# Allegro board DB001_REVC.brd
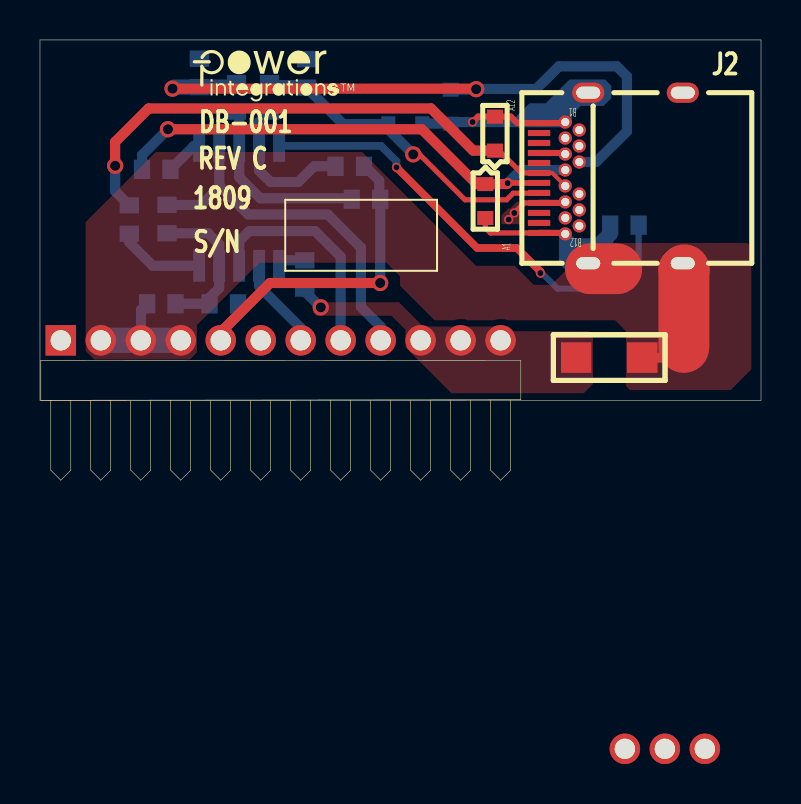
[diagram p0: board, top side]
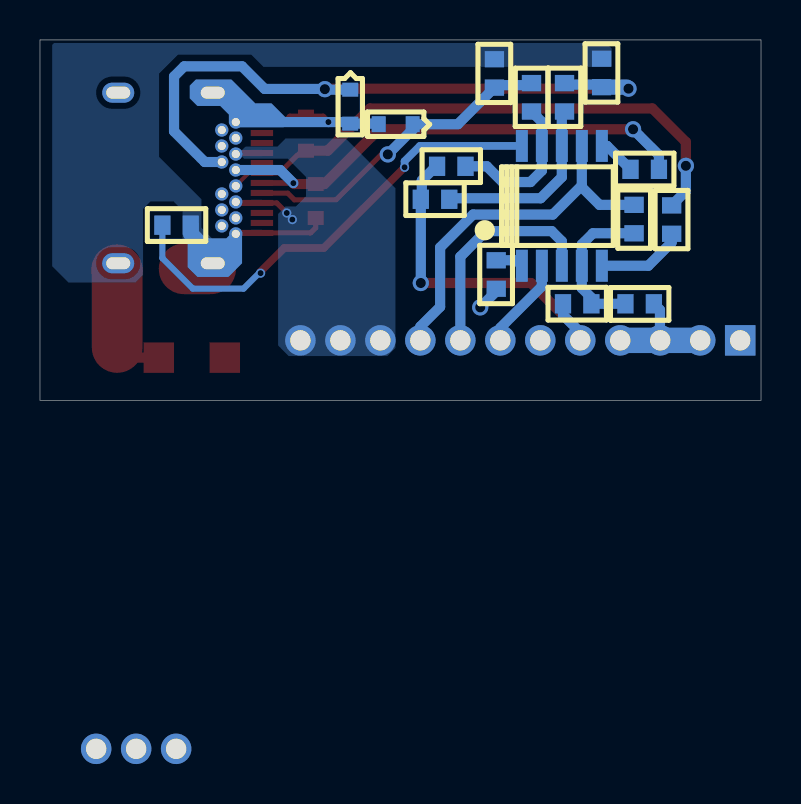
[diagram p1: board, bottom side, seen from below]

Outline 36.07 x 18.03 mm; copper layers: TOP, BOTTOM. Coordinates in mm from the lower left corner of the outline.
Outline path: 0,18.03 0,0 36.07,0 36.07,18.03 0,18.03

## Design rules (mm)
constraint set DEFAULT: min track width 0.508

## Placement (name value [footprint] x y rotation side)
C1  270 pF  [PISMC0603]  13.33 17.07 270 bottom
C2  270 pF  [PISMC0603]  7.98 17.09 270 bottom
C3  2.2 uF  [PISMC1206]  26.82 2.13 0 top
C18  2.2 uF  [PISMC0603]  6.35 8.36 90 bottom
C19  270 pF  [PISMC0603]  14.78 11.71 0 bottom
C20  270 pF  [PISMC0603]  15.6 10.06 0 bottom
D1  DZ2J240M0L  [PI_SM_D_SSMINI2P]  20.55 15.54 270 bottom
D2  DZ2J240M0L  [PI_SM_D_SSMINI2P]  17.42 13.82 0 bottom
D3  DZ2J240M0L  [PI_SM_D_SSMINI2P]  22.28 10.82 270 top
D4  DZ2J240M0L  [PI_SM_D_SSMINI2P]  22.76 12.5 90 top
J1  CON15  [PI_UNSHROUD_2MM_15PRA]  1.04 3 0 bottom
J2  CON24_USB_C  [PI_CONN_USBC_WURTH]  26.97 11.13 90 top
NOREF  -  []  7.09 17.42 0 top
NOREF#2  -  []  0 0 90 top
NOREF#3  -  []  -250.16 -145.39 0 top
NOREF#4  -  []  -172.35 53.62 0 top
NOREF#5  -  []  0 18.03 0 top
R1  22  [PISMR0603]  11.48 14.45 90 bottom
R2  22  [PISMR0603]  9.83 15.88 270 bottom
R3  22  [PISMR0603]  4.47 9.75 270 bottom
R4  22  [PISMR0603]  6.53 11.56 180 bottom
R13  1 k  [PISMR0603]  13.25 7.01 270 bottom
R14  0.0  [PISMR0603]  8.48 4.83 0 bottom
R15  0.0  [PISMR0603]  6.78 4.83 180 bottom
RT1  100 k  [PISMR0603]  28.52 8.76 0 bottom
U1  WT6635P  [PISMSOP10]  11.96 6.73 180 bottom

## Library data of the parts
C1-C3 C18-C20 = CAP NP
D1-D4 = DIODE_ZENER
J1 = CON15
J2 = CON24_USB
R1-R4 R13-R15 = R
RT1 = THERMISTOR
U1 = WT6635P-10

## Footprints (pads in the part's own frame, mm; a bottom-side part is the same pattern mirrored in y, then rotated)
PI_CONN_USBC_WURTH
  oval 1.001x1.6 hole 0.599x1.199: (-4.27,-0.45) (-4.27,-5.179) (4.27,-0.45) (4.27,-5.179)
  round 0.66 hole 0.406: (-1.999,0.701) (1.999,0.701) B1(2.799,0.701) B2(2.4,0) B3(1.6,0) B4(1.199,0.701) B5(0.8,0) B6(0.399,0.701) B7(-0.399,0.701) B8(-0.8,0) B9(-1.199,0.701) B10(-1.6,0) B11(-2.4,0) B12(-2.799,0.701)
  rect 0.305x1.118 smd: A1(-2.751,2.009) A2(-2.25,2.009) A3(-1.75,2.009) A4(-1.25,2.009) A5(-0.749,2.009) A6(-0.249,2.009) A7(0.249,2.009) A8(0.749,2.009) A9(1.25,2.009) A10(1.75,2.009) A11(2.25,2.009) A12(2.751,2.009)
PI_SM_D_SSMINI2P
  rect 0.699x0.8 smd: 1(0,0) 2(1.699,0)
PI_UNSHROUD_2MM_15PRA
  rect 1.524x1.524 hole 1.016: 1(0,0)
  round 1.524 hole 1.016: 2(2,0) 3(4,0) 4(6,0) 5(8,0) 6(10,0) 7(12,0) 8(14,0) 9(16,0) 10(18,0) 11(20,0) 12(22,0) 13(28.216,20.447) 14(30.216,20.447) 15(32.216,20.447)
PISMC0603
  rect 0.813x0.965 smd: 1(0,0) 2(1.422,0)
PISMC1206
  rect 1.524x1.524 smd: 1(0,0) 2(3.302,0)
PISMR0603
  rect 0.813x0.965 smd: 1(0,0) 2(1.422,0)
PISMSOP10
  rect 0.599x1.6 smd: 1(0,0) 2(1.001,0) 3(1.999,0) 4(3,0) 5(4,0) 6(4,5.999) 7(3,5.999) 8(1.999,5.999) 9(1.001,5.999) 10(0,5.999)

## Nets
GND: C1.1 C2.1 C3.2 D1.2 D2.2 D3.2 D4.2 J1.2 J1.3 J1.4 J2.A1 J2.A12 J2.B1 J2.B12 R15.2 RT1.1
GND_SIGNAL: C19.2 C20.2 J1.5 R14.2
VBUS_IN: J1.1
VBUS_OUT: C3.1 J1.10 J1.11 J1.12 J2.A4 J2.A9 J2.B4 J2.B9(VBUS4) R13.2
BPS: J1.6
SCL: J1.7 U1.2
SDA: J1.8 U1.3
UVCC: C18.2 J1.9 U1.7
N12116712: C2.2 D1.1 J2.B5 R2.1
N12116716: C1.2 D2.1 J2.A5 R1.2
N12116772: RT1.2 U1.10
N12116776: D3.1 J2.A6 J2.B6 R4.2
N12116788: R13.1 U1.1
N12116812: D4.1 J2.A7 J2.B7 R3.1
N12116850: C19.1 R1.1 U1.9
N12116916: C20.1 R2.2 U1.8
N12116972: C18.1 R14.1 R15.1 U1.4(VSS)
N12121431: R3.2 U1.5
N12121586: R4.1 U1.6

Pads without a net: J1 13 14 15; J2 A2 A3 A8 A10 A11 B2 B3 B8 B10 B11

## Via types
v1: diameter 0.813, hole 0.508, TOP to BOTTOM, 7 vias
v2: diameter 0.457, hole 0.305, TOP to BOTTOM, 6 vias

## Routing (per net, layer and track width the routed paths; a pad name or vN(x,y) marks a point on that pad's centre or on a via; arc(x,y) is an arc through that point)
GND: length 32.7
  TOP w0.254: J2.A1 22.53,8.37 22.28,8.63 D3.2
  TOP w0.305: J2.A1 26.23,8.37 J2.B12 ; J2.B1 26.23,13.88 J2.A12 23.88,13.88 23.56,14.2 D4.2 21.91,14.2 v2(21.64,13.92)
  TOP w0.508: C3.2 31.7,2.13 32.21,2.64
  TOP w2.54: 27.53,6.58 28.85,6.58 ; 32.21,2.64 32.21,6.5 32.23,6.53
  BOTTOM w0.508: R15.2 5.05,4.52 5.05,3.01 J1.3 ; D2.2 19.15,13.85 D1.2 20.63,13.92 v2(21.64,13.92) J2.B1
  BOTTOM w0.762: RT1.1 28.52,8.33 27.03,6.83
  BOTTOM w1.27: 7.04,3 J1.3 J1.2 3.04,3
GND_SIGNAL: length 17.8
  TOP w0.508: v1(17.02,5.87) 11.51,5.87 9.04,3.4 J1.5
  BOTTOM w0.508: C19.2 16.26,11.71 16.97,11 16.97,10.11 C20.2 v1(17.02,5.87) ; J1.5 9.04,3.4 9.91,4.27 R14.2
VBUS_OUT: length 5.4
  TOP w0.254: v2(23.72,9.37) 24.23,9.88 J2.A4
  TOP w0.305: J2.A9 26.22,12.37 J2.B4 ; J2.A4 26.22,9.88 J2.B9
  BOTTOM w0.508: v1(14.05,4.65) 13.25,5.45 R13.2
  vias: v2(23.44,9.04)
SCL: length 4.6
  BOTTOM w0.254: 13.04,3 J1.7
  BOTTOM w0.508: U1.2 10.96,5.7 13.04,3.62 13.04,3
SDA: length 11.2
  BOTTOM w0.508: J1.8 15.04,7.18 13.76,8.47 10.47,8.47 9.96,7.96 U1.3
UVCC: length 18.5
  BOTTOM w0.508: 8.96,10.75 10.41,9.3 14.4,9.3 16.05,7.65 16.05,4.67 17.04,3.69 J1.9 ; 8.96,10.75 8.96,10.67 8.08,9.78 C18.2 ; 8.96,10.75 U1.7
N12116712: length 33.9
  TOP w0.508: v1(21.82,15.57) 21.79,15.6 v1(6.63,15.6)
  BOTTOM w0.508: D1.1 21.75,15.54 21.82,15.62 ; 21.82,15.62 21.82,15.58 v1(21.82,15.57) ; 21.82,15.62 21.86,15.58 24.83,15.58 25.96,16.71 28.85,16.71 29.36,16.21 29.36,13.46 27.83,11.93 J2.B5 ; C2.2 8.1,15.8 9.75,15.8 R2.1 ; v1(6.63,15.6) 6.71,15.67
  BOTTOM w0.762: 6.71,15.67 C2.2
N12116716: length 16.2
  TOP w0.254: v1(18.67,12.31) 18.99,12.31 21.26,10.03 23.34,10.03 23.67,10.36 24.95,10.36 J2.A5
  BOTTOM w0.508: v1(18.67,12.31) 17.42,13.55 D2.1 15.16,13.82 C1.2 13.21,15.77 11.58,15.77 R1.2
N12116772: length 23.4
  TOP w0.381: v2(17.83,11.66) 21.87,7.62 23.85,7.62 25.03,6.44 v2(25.03,6.36)
  BOTTOM w0.305: v2(25.03,6.36) 25.11,6.36 25.88,5.59 28.42,5.59 29.95,7.11 RT1.2
  BOTTOM w0.381: v2(17.83,11.66) 17.83,11.96 17.06,12.73 U1.10
N12116776: length 27.1
  TOP w0.254: 23.31,10.87 23.32,10.87 24.96,10.87 J2.A6 23.4,10.88 v2(23.39,10.87)
  TOP w0.508: 23.39,10.87 v2(23.39,10.87) 23.35,10.82 D3.1 21.84,10.82 19.1,13.56 v1(6.4,13.56)
  BOTTOM w0.508: v2(23.39,10.87) 24.05,11.52 J2.B6 ; v1(6.4,13.56) 5.11,12.27 R4.2
N12116788: length 1.4
  BOTTOM w0.508: U1.1 12.24,7.01 R13.1
N12116812: length 28.3
  TOP w0.203: J2.A7 25.63,11.37 J2.B7
  TOP w0.254: J2.A7 24.08,11.37 22.96,12.5 D4.1
  TOP w0.508: v1(3.76,11.73) 3.76,12.93 5.44,14.61 19.56,14.61 21.67,12.5 D4.1
  BOTTOM w0.508: R3.1 3.76,10.46 v1(3.76,11.73)
N12116850: length 7.6
  BOTTOM w0.508: R1.1 10.96,13.93 U1.9 10.96,11.49 11.53,10.92 12.93,10.92 13.72,11.71 C19.1
N12116916: length 9.4
  BOTTOM w0.508: C20.1 15.54,10.11 11.02,10.11 9.96,11.17 U1.8 9.96,14.32 R2.2
N12116972: length 7.7
  BOTTOM w0.508: R15.1 R14.1 8.48,5.13 8.96,5.61 U1.4 8.96,7.8 8.41,8.36 C18.1
N12121431: length 4.4
  BOTTOM w0.508: U1.5 5.64,6.73 4.47,7.9 R3.2
N12121586: length 1.9
  BOTTOM w0.508: U1.6 7.7,12.73 R4.1

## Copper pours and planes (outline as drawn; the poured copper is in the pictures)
GND on BOTTOM (solid shape): 26.52,8.43 26.52,8.33 26.75,8.1 28.55,8.1 28.68,7.98 28.68,6.65 28.19,6.17 26.64,6.17 25.96,6.86 25.96,8.41 26.11,8.56 26.39,8.56
GND on BOTTOM (solid shape): 28.57,15.75 28.57,15.11 28.19,14.73 27.05,14.73 26.62,14.3 26.62,13.87 26.42,13.67 23.88,13.67 23.7,13.84 23.7,14.07 24.49,14.86 25.3,14.86 26.49,16.05 28.27,16.05
GND on TOP: 7.85,3.76 7.85,2.39 7.49,2.03 2.72,2.03 2.29,2.46 2.29,8.92 5.79,12.42 16.13,12.42 21.82,6.73 23.75,6.73 24.7,5.78 25.6,5.78 25.6,5.79 26.28,6.46 26.28,6.97 27.18,7.87 35.38,7.87 35.59,7.67 35.59,1.55 34.54,0.51 29.51,0.51 29.31,0.71 29.31,3.45 28.77,4 19.75,4 18,5.75 18.01,5.77 18.01,6.2 17.32,6.88 11.02,6.88 11,6.91
GND on BOTTOM: 27.3,7.75 27.2,7.85 27.99,8.64 27.99,10.06 30.11,12.18 30.11,16.34 29.16,17.3 25.5,17.3 24.89,16.69 7.49,16.69 7.47,16.71 7.47,17.6 7.75,17.88 35.36,17.88 35.46,17.78 35.46,6.71 34.65,5.89 31.29,5.89 30.91,6.27 30.91,9.58 30.53,9.96 29.39,9.96 28.93,9.5 28.93,8 28.68,7.75
VBUS_OUT on TOP: 23.44,3.7 23.69,3.45 27.46,3.45 27.66,3.25 27.66,0.81 27.2,0.36 20.57,0.36 18.29,2.64 18.29,3.52 17.58,4.23 13.83,4.23 13.67,4.39 13.67,4.88 13.84,5.05 14.2,5.05 14.35,4.9 17.96,4.9 19.16,3.7
VBUS_OUT on TOP: 25.53,10.01 23.83,10.01 23.09,9.27 23.09,8.76 23.19,8.66 24.03,8.66 24.08,8.71 24.08,9.5 24.31,9.73 25.5,9.73 25.53,9.75
VBUS_OUT on BOTTOM: 24.18,12.7 25.78,12.7 25.96,12.52 26.37,12.52 26.37,12.17 25.93,12.17 25.86,12.09 23.67,12.09 22.76,11.18 22.76,10.21 23.27,9.7 23.77,9.7 24.16,9.32 24.16,2.74 23.62,2.21 18.69,2.21 18.29,2.62 18.29,10.62 20.78,13.11 23.77,13.11

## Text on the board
Ref Des/Silkscreen Top: 1809 | S/N | REV C | DB-001
User.7: PLESE DELETE THESE PINS | SLOTS | 14.  FAB HOUSE LOGO,DATE CODE TO BE IN SILK SCREEN ONLY.DO NOT USE COPPER. | 13.  MATERIAL FR4 COPPER 2oz THICKNESS 0.062"
User.9: FIGURE | FINISHED_SIZE | 12.0 | 16.0 | 20.0 | 40.0 | 47.201x23.598 | DRILL CHART: TOP to BOTTOM | ALL UNITS ARE IN MILS | TOLERANCE_DRILL | +3.0/-3.0 | +0.0/-0.0 | PLATED | QTY | 6 | 14 | 7 | 15 | 4
